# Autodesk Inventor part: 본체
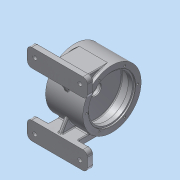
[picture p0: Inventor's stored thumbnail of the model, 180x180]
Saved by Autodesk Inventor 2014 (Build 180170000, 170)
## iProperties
Created: 2025-12
Part Number: 본체
Material: 알루미늄 6061
Document SubType Name: Modeling
Designer: dg
Density: 2.71 g/cm^3
Appearance: 알루미늄 - 평지
Mass: 5647.33 g
Surface Area: 3055.99 cm^2
Volume: 2083.89 cm^3
Author: dg
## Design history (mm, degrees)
sketch "스케치1"
  geometry: L1 (-62, 0)-(62, 0); L2 (-62, 78)-(-57, 78); L3 (-57, 78)-(-57, 73); L4 (-57, 73)-(-40, 73); L5 (-40, 73)-(-40, 87); L6 (-40, 87)-(-8, 87); L7 (-8, 87)-(-8, 0); L8 (-8, 0)-(8, 0); L9 (8, 0)-(8, 87); L10 (8, 87)-(40, 87); L11 (40, 87)-(40, 73); L12 (40, 73)-(57, 73); L13 (57, 73)-(57, 78); L14 (57, 78)-(62, 78); L15 (62, 78)-(62, 97); L16 (62, 97)-(-62, 97); L17 (-62, 97)-(-62, 78); 2 further points
  constraints: 34 end point, 11 parallel, 4 perpendicular, 3 collinear, 3 horizontal alignment, 2 coincident, 2 point on line, 2 vertical alignment, 1 horizontal, 1 midpoint
  dimensions: "d0" = 124 distance of L1.start L1.end; "d1" = 146 diameter of L4 L1; "d2" = 156 diameter of L2 L1; "d3" = 174 diameter of L6 L1; "d4" = 194 diameter of L16 L1; "d5" = 5 distance of L2.start L2.end; "d7" = 32 distance of L5.end L6.end; "d48" = 22 distance between parallel lines of L5 L17
revolve "회전1" sketch "스케치1" stored, may be unused: angle "d8" = 90 deg
sketch "스케치2"
  geometry: L1 (0, -97)-(-100, -97); L2 (-100, -97)-(-100, -75); L3 (-100, -75)-(-61.514, -75); A1 r 97 centre (0, 0) between (0, -97) and (-61.514, -75) reference; 1 further point
  constraints: 6 end point, 2 point on circle, 1 horizontal, 1 parallel, 1 perpendicular, 1 tangent
  dimensions: "d9" = 22 distance of L1.end L2.end; "d10" = 100 distance from line of L2 L1.start
extrude "돌출1" join sketch "스케치2" stored distance "d11" = 100; taper "d12" = 0 deg
sketch "스케치3"
  geometry: L1 (-50, 22)-(150, 22); L2 (150, 22)-(150, -38); L3 (150, -38)-(-50, -38); L4 (-50, -38)-(-50, 22); 3 further points
  constraints: 8 end point, 2 parallel, 1 horizontal, 1 horizontal alignment, 1 midpoint, 1 perpendicular, 1 vertical alignment
  dimensions: "d13" = 200 distance of L2.end L3.end; "d14" = 60 distance of L3.end L1.start
extrude "돌출2" join sketch "스케치3" distance "d15" = 20; taper "d16" = 0 deg
sketch "스케치4"
  geometry: L1 (-100, -75)-(-61.514, -75) reference; L2 (-100, -75)-(-120, -75) reference; L3 (-112, -75)-(-89.83, -36.6); A1 r 97 centre (0, 0) between (-61.514, -75) and (-89.83, -36.6) reference; 1 further point
  constraints: 2 end point, 1 point on circle, 1 point on line
  dimensions: "d17" = 60 deg angle of L1 L3; "d18" = 8 distance of L2.end L3.start
extrude "돌출3" join sketch "스케치4" stored distance "d19" = 12; taper "d20" = 0 deg
fillet "모깎기1" dims "d21" = 15
sketch "스케치5"
  geometry: 3 further points
  constraints: 1 horizontal alignment
  dimensions: "d22" = 150 distance of point (125, 13) point (-25, 13); "d23" = 75 horizontal distance of point (50, -97) point (-25, 13); "d24" = 110 vertical distance of point (50, -97) point (125, 13)
hole "구멍1" sketch "스케치5" at (-25, 13), (125, 13) diameter "d25" = 13.5; stored, may be unused: countersink angle "d29" = 90 deg, drill point angle "d31" = 118 deg; dims "d26" = 6, "d27" = 33, "d28" = 2, "d30" = 8
fillet "모깎기2" dims "d32" = 3
fillet "모깎기3" dims "d33" = 3
fillet "모깎기4" dims "d34" = 3
fillet "모깎기5" dims "d35" = 3
fillet "모깎기6" dims "d36" = 3
fillet "모깎기7" dims "d37" = 3
fillet "모깎기8" dims "d38" = 3
fillet "모깎기9" dims "d39" = 3
fillet "모깎기10" dims "d40" = 3
fillet "모깎기11" dims "d41" = 3
fillet "모깎기12" dims "d42" = 3
fillet "모깎기13" dims "d43" = 3
sketch "스케치6"
  geometry: L1 (23.383, -39)-(37.148, -62.842); L2 (-23.383, -39)-(-37.148, -62.842); L3 (0, -25.5)-(0, -73); A1 r 73 centre (0, 0) between (37.148, -62.842) and (-37.148, -62.842) reference; A2 r 27 centre (0, -52.5) between (23.383, -39) and (-23.383, -39); 1 further point
  constraints: 6 end point, 6 point on circle, 2 tangent, 2 vertical alignment, 1 centre point, 1 midpoint, 1 vertical
  dimensions: "d44" = 54 diameter of A2; "d45" = 52.5 distance of A1.centre A2.centre; "d46" = 30 deg angle of L1 L3; "d47" = 30 deg angle of L3 L2
extrude "돌출4" join sketch "스케치6" distance "d49" = 17; taper "d50" = 0 deg
sketch "스케치7"
  geometry: A1 r 27 centre (0, -52.5) between (23.383, -39) and (-23.383, -39) reference; 1 further point
  constraints: 1 coincident
hole "구멍2" sketch "스케치7" at (0, -52.5) diameter "d51" = 42; stored, may be unused: countersink angle "d55" = 90 deg, drill point angle "d57" = 0 deg; dims "d52" = 6, "d53" = 33, "d54" = 2, "d56" = 3.05
hole "구멍3" diameter "d60" = 42; stored, may be unused: countersink angle "d64" = 90 deg, drill point angle "d66" = 0 deg; dims "d61" = 6, "d62" = 44.5, "d63" = 1.95, "d65" = 12, "d103" = 10, "d104" = 10
sketch "스케치9"
  geometry: C1 r 78 at (0, 0) reference; 1 further point
  constraints: 1 vertical alignment
  dimensions: "d67" = 85 distance of C1.centre point (0, 85)
hole "구멍4" sketch "스케치9" at (0, 85) diameter "d68" = 6.647; stored, may be unused: countersink angle "d72" = 90 deg, drill point angle "d74" = 118 deg; dims "d69" = 16, "d70" = 44.5, "d71" = 1.95, "d73" = 18
chamfer "모따기1" distance "d78" = 1; stored, may be unused: second distance "d79" = 2, angle "d80" = 45 deg
chamfer "모따기2" distance "d81" = 1; stored, may be unused: second distance "d82" = 2, angle "d83" = 45 deg
sketch "스케치10"
  geometry: C1 r 87 at (0, 0) reference; 2 further points
  constraints: 1 coincident, 1 vertical alignment
  dimensions: "d84" = 52.5 distance of point (0, -52.5) point (0, 0)
hole "구멍5" sketch "스케치10" at (0, 0), (0, -52.5) diameter "d85" = 38; stored, may be unused: countersink angle "d89" = 90 deg, drill point angle "d91" = 118 deg; dims "d86" = 16, "d87" = 42, "d88" = 12, "d90" = 18
chamfer "모따기3" distance "d92" = 1; stored, may be unused: second distance "d93" = 2, angle "d94" = 45 deg
fillet "모깎기14" dims "d95" = 0.6
fillet "모깎기15" dims "d96" = 3
fillet "모깎기16" dims "d97" = 3
fillet "모깎기17" dims "d98" = 3
fillet "모깎기18" dims "d99" = 3
node "작업 평면1"
sketch "스케치11"
  geometry: L1 (-53, 75.66)-(-53, 91.18) reference; L2 (-9, 69.84)-(-47, 69.84) reference; L3 (-9, 41.914)-(-9, 69.84) reference; L4 (3, 35.269)-(-3, 35.269) reference; L5 (9, 69.84)-(9, 41.914) reference; L6 (47, 69.84)-(9, 69.84) reference; L7 (53, 91.18)-(53, 75.66) reference; L8 (47, 97)-(-47, 97) reference; L9 (53, -75.66)-(53, -91.18) reference; L10 (9, -69.84)-(47, -69.84) reference; L11 (9, -41.914)-(9, -69.84) reference; L12 (-3, -35.269)-(3, -35.269) reference; L13 (-9, -69.84)-(-9, -41.914) reference; L14 (-47, -69.84)-(-9, -69.84) reference; L15 (-53, -91.18)-(-53, -75.66) reference; L16 (47, -97)-(-47, -97) reference; L17 (62, 97)-(62, -97) reference; L18 (-62, 97)-(-62, -97) reference; 3 further points
  constraints: 1 coincident, 1 horizontal alignment, 1 midpoint, 13 other
feature "엠보싱1" sketch "스케치11" dims "d101" = 0.5, "d102" = 0
node "솔리드1"
mirror "대칭1"
pattern_circular "원형 패턴1" dims angle "d76" = 360 deg
mirror "대칭2"
node "투영된 루프1"
other parameters: "d100" = 97
